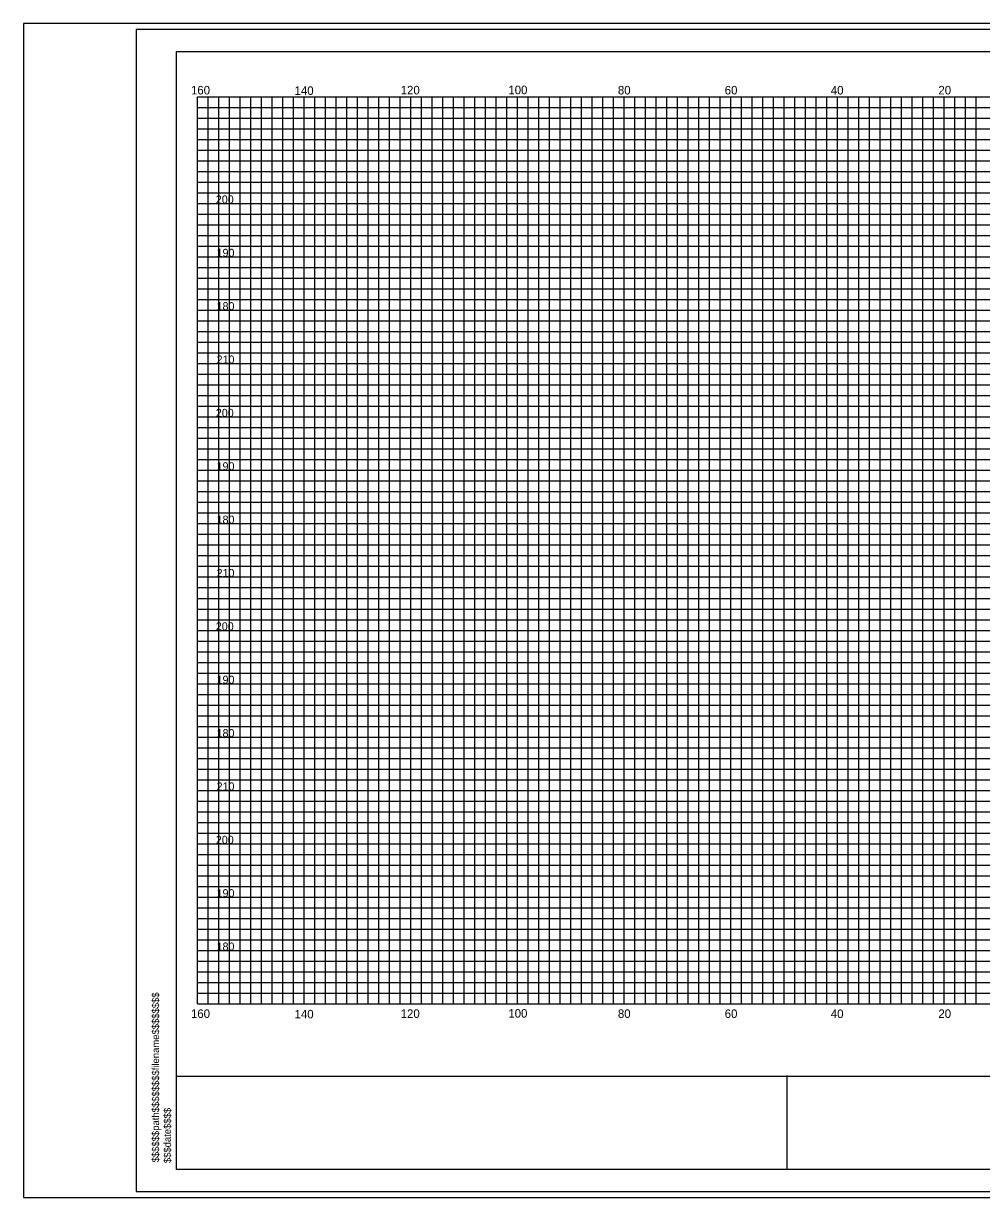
# Model space of a CAD drawing. Extents: x 967 to 1326, y 964 to 2584.
# Drawn here: x 967.4 to 1147, y 963.7 to 1183.7 of the extents above; entities that cross this region are included whole.
import ezdxf

# ---------------------------------------------------------------- set-up
doc = ezdxf.new("R2010")
doc.units = 0
for name, color, linetype in [('Default', 7, 'Continuous'), ('RD_SHT_Bndy', 7, 'Continuous'), ('RD_SHT_IplotShp', 7, 'Continuous'), ('RD_SHT_MjGrid', 7, 'Continuous'), ('RD_SHT_MnGrid', 7, 'Continuous'), ('RD_SHT_TX', 7, 'Continuous'), ('RD_Sketch1', 7, 'Continuous')]:
    doc.layers.add(name, color=color, linetype=linetype)

msp = doc.modelspace()

# ---------------------------------------------------------------- linework, layer by layer
at = {"layer": 'RD_SHT_Bndy'}
for p, q in [((996.11, 968.98), (996.11, 1178.46)), ((996.11, 1178.46), (1323.89, 1178.46)), ((996.11, 986.49), (1323.89, 986.49)), ((1110.59, 968.98), (1110.59, 986.56)), ((1323.89, 968.98), (996.11, 968.98))]:
    msp.add_line(p, q, dxfattribs=at)
at = {"layer": 'RD_SHT_IplotShp'}
for points in [[(967.41, 963.72), (1326.28, 963.72), (1326.28, 1183.72), (967.41, 1183.72)], [(988.52, 964.84), (1326.28, 964.84), (1326.28, 1182.6), (988.52, 1182.6)]]:
    msp.add_lwpolyline(points, close=True, dxfattribs=at)
at = {"layer": 'RD_SHT_MjGrid'}
for p, q in [((1000, 1170), (1320, 1170)), ((1000, 1000), (1000, 1170)), ((1010, 1000), (1010, 1170)), ((1020, 1000), (1020, 1170)), ((1030, 1000), (1030, 1170)), ((1040, 1000), (1040, 1170)), ((1050, 1000), (1050, 1170)), ((1060, 1000), (1060, 1170)), ((1070, 1000), (1070, 1170)), ((1080, 1000), (1080, 1170)), ((1090, 1000), (1090, 1170)), ((1100, 1000), (1100, 1170)), ((1110, 1000), (1110, 1170)), ((1120, 1000), (1120, 1170)), ((1130, 1000), (1130, 1170)), ((1140, 1000), (1140, 1170)), ((1000, 1160), (1320, 1160)), ((1000, 1150), (1320, 1150)), ((1000, 1140), (1320, 1140)), ((1000, 1130), (1320, 1130)), ((1000, 1120), (1320, 1120)), ((1000, 1110), (1320, 1110)), ((1000, 1100), (1320, 1100)), ((1000, 1090), (1320, 1090)), ((1000, 1080), (1320, 1080)), ((1000, 1070), (1320, 1070)), ((1000, 1060), (1320, 1060)), ((1000, 1050), (1320, 1050)), ((1000, 1040), (1320, 1040)), ((1000, 1030), (1320, 1030)), ((1000, 1020), (1320, 1020)), ((1000, 1010), (1320, 1010)), ((1000, 1000), (1320, 1000))]:
    msp.add_line(p, q, dxfattribs=at)
at = {"layer": 'RD_SHT_MnGrid'}
for p, q in [((1002, 1000), (1002, 1170)), ((1004, 1000), (1004, 1170)), ((1006, 1000), (1006, 1170)), ((1008, 1000), (1008, 1170)), ((1012, 1000), (1012, 1170)), ((1014, 1000), (1014, 1170)), ((1016, 1000), (1016, 1170)), ((1018, 1000), (1018, 1170)), ((1022, 1000), (1022, 1170)), ((1024, 1000), (1024, 1170)), ((1026, 1000), (1026, 1170)), ((1028, 1000), (1028, 1170)), ((1032, 1000), (1032, 1170)), ((1034, 1000), (1034, 1170)), ((1036, 1000), (1036, 1170)), ((1038, 1000), (1038, 1170)), ((1042, 1000), (1042, 1170)), ((1044, 1000), (1044, 1170)), ((1046, 1000), (1046, 1170)), ((1048, 1000), (1048, 1170)), ((1052, 1000), (1052, 1170)), ((1054, 1000), (1054, 1170)), ((1056, 1000), (1056, 1170)), ((1058, 1000), (1058, 1170)), ((1062, 1000), (1062, 1170)), ((1064, 1000), (1064, 1170)), ((1066, 1000), (1066, 1170)), ((1068, 1000), (1068, 1170)), ((1072, 1000), (1072, 1170)), ((1074, 1000), (1074, 1170)), ((1076, 1000), (1076, 1170)), ((1078, 1000), (1078, 1170)), ((1082, 1000), (1082, 1170)), ((1084, 1000), (1084, 1170)), ((1086, 1000), (1086, 1170)), ((1088, 1000), (1088, 1170)), ((1092, 1000), (1092, 1170)), ((1094, 1000), (1094, 1170)), ((1096, 1000), (1096, 1170)), ((1098, 1000), (1098, 1170)), ((1102, 1000), (1102, 1170)), ((1104, 1000), (1104, 1170)), ((1106, 1000), (1106, 1170)), ((1108, 1000), (1108, 1170)), ((1112, 1000), (1112, 1170)), ((1114, 1000), (1114, 1170)), ((1116, 1000), (1116, 1170)), ((1118, 1000), (1118, 1170)), ((1122, 1000), (1122, 1170)), ((1124, 1000), (1124, 1170)), ((1126, 1000), (1126, 1170)), ((1128, 1000), (1128, 1170)), ((1132, 1000), (1132, 1170)), ((1134, 1000), (1134, 1170)), ((1136, 1000), (1136, 1170)), ((1138, 1000), (1138, 1170)), ((1142, 1000), (1142, 1170)), ((1144, 1000), (1144, 1170)), ((1146, 1000), (1146, 1170)), ((1000, 1168), (1320, 1168)), ((1000, 1166), (1320, 1166)), ((1000, 1164), (1320, 1164)), ((1000, 1162), (1320, 1162)), ((1000, 1158), (1320, 1158)), ((1000, 1156), (1320, 1156)), ((1000, 1154), (1320, 1154)), ((1000, 1152), (1320, 1152)), ((1000, 1148), (1320, 1148)), ((1000, 1146), (1320, 1146)), ((1000, 1144), (1320, 1144)), ((1000, 1142), (1320, 1142)), ((1000, 1138), (1320, 1138)), ((1000, 1136), (1320, 1136)), ((1000, 1134), (1320, 1134)), ((1000, 1132), (1320, 1132)), ((1000, 1128), (1320, 1128)), ((1000, 1126), (1320, 1126)), ((1000, 1124), (1320, 1124)), ((1000, 1122), (1320, 1122)), ((1000, 1118), (1320, 1118)), ((1000, 1116), (1320, 1116)), ((1000, 1114), (1320, 1114)), ((1000, 1112), (1320, 1112)), ((1000, 1108), (1320, 1108)), ((1000, 1106), (1320, 1106)), ((1000, 1104), (1320, 1104)), ((1000, 1102), (1320, 1102)), ((1000, 1098), (1320, 1098)), ((1000, 1096), (1320, 1096)), ((1000, 1094), (1320, 1094)), ((1000, 1092), (1320, 1092)), ((1000, 1088), (1320, 1088)), ((1000, 1086), (1320, 1086)), ((1000, 1084), (1320, 1084)), ((1000, 1082), (1320, 1082)), ((1000, 1078), (1320, 1078)), ((1000, 1076), (1320, 1076)), ((1000, 1074), (1320, 1074)), ((1000, 1072), (1320, 1072)), ((1000, 1068), (1320, 1068)), ((1000, 1066), (1320, 1066)), ((1000, 1064), (1320, 1064)), ((1000, 1062), (1320, 1062)), ((1000, 1058), (1320, 1058)), ((1000, 1056), (1320, 1056)), ((1000, 1054), (1320, 1054)), ((1000, 1052), (1320, 1052)), ((1000, 1048), (1320, 1048)), ((1000, 1046), (1320, 1046)), ((1000, 1044), (1320, 1044)), ((1000, 1042), (1320, 1042)), ((1000, 1038), (1320, 1038)), ((1000, 1036), (1320, 1036)), ((1000, 1034), (1320, 1034)), ((1000, 1032), (1320, 1032)), ((1000, 1028), (1320, 1028)), ((1000, 1026), (1320, 1026)), ((1000, 1024), (1320, 1024)), ((1000, 1022), (1320, 1022)), ((1000, 1018), (1320, 1018)), ((1000, 1016), (1320, 1016)), ((1000, 1014), (1320, 1014)), ((1000, 1012), (1320, 1012)), ((1000, 1008), (1320, 1008)), ((1000, 1006), (1320, 1006)), ((1000, 1004), (1320, 1004)), ((1000, 1002), (1320, 1002))]:
    msp.add_line(p, q, dxfattribs=at)
at = {"layer": 'RD_Sketch1'}
msp.add_lwpolyline([(967.41, 963.72), (1326.28, 963.72), (1326.28, 1183.72), (967.41, 1183.72)], close=True, dxfattribs=at)

# ---------------------------------------------------------------- texts
at = {"layer": 'Default'}
for s, p in [('200', (1003.47, 1150)), ('190', (1003.61, 1140)), ('180', (1003.61, 1130)), ('210', (1003.61, 1120)), ('200', (1003.47, 1110)), ('190', (1003.61, 1100)), ('180', (1003.61, 1090)), ('210', (1003.61, 1080)), ('200', (1003.47, 1070)), ('190', (1003.61, 1060)), ('180', (1003.61, 1050)), ('210', (1003.61, 1040)), ('200', (1003.47, 1030)), ('190', (1003.61, 1020)), ('180', (1003.61, 1010))]:
    msp.add_text(s, height=1.5, dxfattribs=at).set_placement(p)
for s, p in [('$$$$$$path$$$$$$$$filename$$$$$$$$', (992.83, 970.31)), ('$$$date$$$$', (995.04, 970.17))]:
    msp.add_text(s, height=1.3258, rotation=90, dxfattribs=at).set_placement(p)
at = {"layer": 'RD_SHT_TX'}
for s, p in [('160', (998.81, 1170.42)), ('140', (1018.23, 1170.34)), ('120', (1038.12, 1170.43)), ('100', (1058.3, 1170.47)), ('80', (1078.84, 1170.42)), ('60', (1098.86, 1170.42)), ('40', (1118.75, 1170.41)), ('20', (1138.91, 1170.42)), ('160', (998.81, 997.37)), ('140', (1018.23, 997.29)), ('120', (1038.12, 997.38)), ('100', (1058.3, 997.42)), ('80', (1078.84, 997.37)), ('60', (1098.86, 997.37)), ('40', (1118.75, 997.36)), ('20', (1138.91, 997.37))]:
    msp.add_text(s, height=1.6, dxfattribs=at).set_placement(p)

doc.saveas('drawing.dxf')
